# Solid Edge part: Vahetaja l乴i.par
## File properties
Author: Türk
Template: Iso Part.par
Last saved by: Türk
Revision: 12
Application: Solid Edge
Accuracy: 0,990
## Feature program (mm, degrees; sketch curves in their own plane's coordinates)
pattern "PatternOccurrence_4"  XOffset = 12 deg
pattern "PatternOccurrence_5"  XOffset = 12 deg
pattern "PatternOccurrence_6"  XOffset = 12 deg
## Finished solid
Body 1: sheet body, 2 faces, 28 edges, 28 vertices.
  Faces by surface: plane 2
  Edges by curve: line 28
Body 2: solid body, 249 faces, 728 edges, 480 vertices.
  Faces by surface: plane 154, cylinder 93, cone 2
  Edges by curve: line 420, circle 308
Bounding box of the edges (mm): 50.000 x 20.000 x 50.000, from (-25, -10, -25) to (25, 10, 25).
Cylindrical faces by radius (mm): R1.068 x60, R15 x30, R22.5 x1, R25 x2
Conical faces (half-angle, radius in mm at the cone's reference point): 45 deg R23 x1, 45 deg R25 x1
Planar faces by outward normal: +x 1, +y 32, +z 2, -x 1, -y 32, -z 2, oblique 84
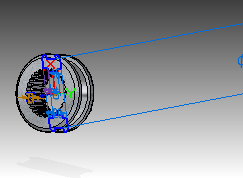
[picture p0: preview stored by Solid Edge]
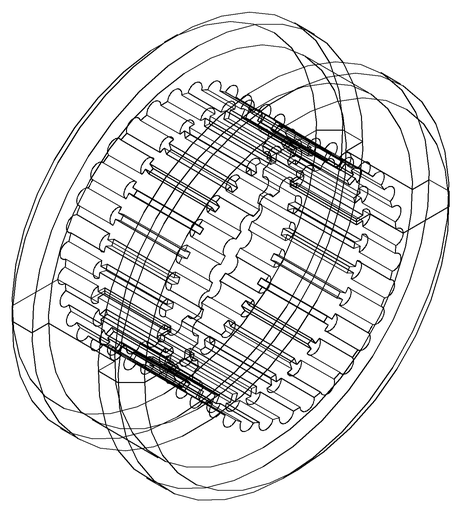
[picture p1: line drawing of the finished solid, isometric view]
